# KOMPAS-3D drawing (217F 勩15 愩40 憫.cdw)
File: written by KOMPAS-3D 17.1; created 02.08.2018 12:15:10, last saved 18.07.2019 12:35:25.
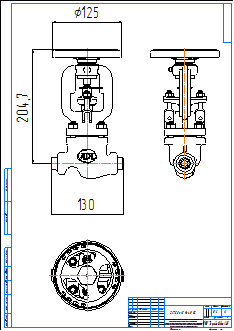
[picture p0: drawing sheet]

Sheet 1: A2, portrait

Title block, sheet 1: name: 217F Ду15 Ру40 СС; material: Внимание! Данный продукт является объектом авторского права ООО «Торговый Дом АДЛ». / Запрещается изменение, копирование, распространение / (в том числе путем копирования на другие сайты и ресурсы в Интернете) / или любое иное использование информации и объектов без предварительного / согласия правообладателя (ООО «Торговый Дом АДЛ»).; mass: 0,6; sheets: 1; organisation: ООО "Торговый дом АДЛ"; sheet format: A2; stored path: \\adlc.lan\data\АДЛ_ПКД\3D-модели\Поставщики\Zetkama\Вентили\217F\KOMPAS 2D\217F Ду15 Ру40 СС.cdw

Views: Вид 1, Проекционный вид 2, Проекционный вид 3
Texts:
  kka
  adl
Dimensions and other numbers on the sheet: 130; 204,7; 125; 1:1; 1; 217F Ду15 Ру40 СС; 0,6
